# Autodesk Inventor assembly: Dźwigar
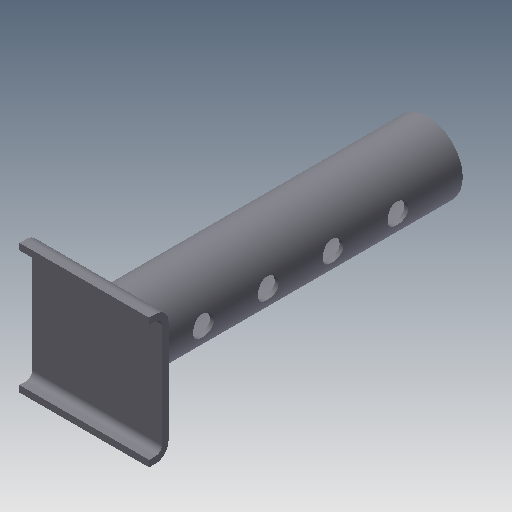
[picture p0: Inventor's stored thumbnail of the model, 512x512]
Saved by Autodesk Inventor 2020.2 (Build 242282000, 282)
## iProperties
Created: 2011-11
Part Number: Dźwigar
Document SubType Name: Assembly
Designer: F.Stasiak
Catalog Web Link: www.expertbooks.pl
Manager: www.cadconsulting.pl
Company: Fabian Stasiak CAD Consulting
Author: F.Stasiak
Subject: Zbiór ćwiczeń. Autodesk Inventor 2020. Kurs Professional
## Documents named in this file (3)
- C:\2020_Kurs_Professional\R4 MES\Podpora\Dźwigar.iam
- C:\2020_Kurs_Professional\R4 MES\Podpora\Rura dźwigara.ipt
- C:\2020_Kurs_Professional\R4 MES\Podpora\Stopka.ipt
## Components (2 placed, 2 different names)
1. Rura dźwigara:1 — Zestawiający:1, Zestawiający:2
2. Stopka:1 — Równoległy:1, Zestawiający:1, Zestawiający:2
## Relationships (3: Mate 2, Flush 1)
- Równoległy:1 [Flush]: Stopka:1
- Zestawiający:1 [Mate]: Rura dźwigara:1 ↔ Stopka:1
- Zestawiający:2 [Mate]: Rura dźwigara:1 ↔ Stopka:1
